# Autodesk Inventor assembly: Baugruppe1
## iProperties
Created: 2006-11
Part Number: Baugruppe1
Cost Center: 7,33 kg
Document SubType Name: Assembly
Designer: E. Rappsilber
Authority: 933110,4 mm^3
SaveDate: 2006-11-14
SaveTime: 13:26
FileName: Baugruppe1
GesamtGewicht: 7,33 kg
GesamtVolumen: 933110,4 mm^3
Author: E. Rappsilber
